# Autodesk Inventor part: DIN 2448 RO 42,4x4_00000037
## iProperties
Created: 2006-02
Part Number: DIN 2448 RO 42,4x4_00000037
Material: Default
Document SubType Name: Modeling
Designer: FranzK
Stock Number: DIN 2448 RO 42,4x4
Mass: 332.959 g
Surface Area: 1674.44 cm^2
Volume: 332.959 cm^3
Density: 1 g/cm^3
G_L: 690.000 mm
G_W: 42.400 mm
G_H: 42.400 mm
AFG_Item: 42.4 x 4
CSToolsMass: 0.3
CSToolsVolume: 332959.0
CSToolsArea: 1674.0
Author: FranzK
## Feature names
1. AFG_Detailed_DIN 2448 RO 42,4x4_00000037 [Extrusion]
2. AFG_Simplified_DIN 2448 RO 42,4x4_00000037 [Extrusion]
